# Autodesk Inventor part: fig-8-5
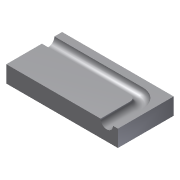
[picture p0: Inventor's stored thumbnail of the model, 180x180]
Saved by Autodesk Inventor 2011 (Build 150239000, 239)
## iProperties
Created: 2009-04
Part Number: fig-8-5
Document SubType Name: Modeling
Designer: Sham
Density: 1 g/cm^3
Author: Sham
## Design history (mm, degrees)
sketch "Sketch1"
  geometry: L1 (-20, 20)-(20, 20); L2 (20, 20)-(20, 0); L3 (20, 0)-(-20, 0); L4 (-20, 0)-(-20, 20)
  constraints: 8 end point
extrude "Extrusion1" new body sketch "Sketch1" distance "d0" = 6; taper "d1" = 0 deg
sketch "Sketch4"
  geometry: L1 (6, 0)-(6, 20) reference; C1 r 2.236 at (6, 15)
  constraints: 1 centre point, 1 point on line
sketch "Sketch5"
  geometry: L1 (-20, 0)-(-20, 20) reference; L2 (20, 0)-(-20, 0) reference; L3 (-20, 15)-(11.667, 15); L4 (16, 10.667)-(16, 0); A1 r 4.333 centre (11.667, 10.667) between (16, 10.667) and (11.667, 15)
  constraints: 4 end point, 2 point on circle, 2 point on line, 1 centre point, 1 tangent
sweep "Sweep5" sketch "Sketch4", "Sketch5" dims "d6" = 0
body "Solid1"
